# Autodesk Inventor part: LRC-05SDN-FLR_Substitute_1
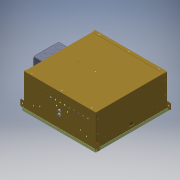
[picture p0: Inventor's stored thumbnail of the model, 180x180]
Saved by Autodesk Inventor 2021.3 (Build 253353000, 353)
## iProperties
Part Number: LRC-05SDN-FLR_Substitute_1
Material: Generic
Document SubType Name: Modeling
Designer: JChurch
Manufacturer: Standard
Standards Organization: Custom
Density: 1 g/cm^3
Appearance: Smooth - Black
Author: JChurch
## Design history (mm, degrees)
derived "LRC-05SDN-FLR.iam"
body "Solid9"
node "830399-00-00.ipt:1"
node "881088-00-00.iam:1::830140-00-00.ipt:1"
body "Solid10"
node "881088-00-00.iam:1::850014-00-00.iam:1::805044-00-00.ipt:1"
body "Solid11"
node "881088-00-00.iam:1::850014-00-00.iam:1::805174-00-00.ipt:1"
body "Solid12"
node "881088-00-00.iam:1::850014-00-00.iam:1::502055-00-00.ipt:1"
body "Solid13"
node "881088-00-00.iam:1::850014-00-00.iam:1::502055-00-00.ipt:2"
body "Solid14"
node "881088-00-00.iam:1::850014-00-00.iam:1::507032-00-00.ipt:1"
body "Solid15"
node "881088-00-00.iam:1::507000-00-00.ipt:1"
body "Solid16"
node "881088-00-00.iam:1::507000-00-00.ipt:2"
body "Solid17"
node "881088-00-00.iam:1::506002-00-00.ipt:1"
body "Solid18"
node "881088-00-00.iam:1::506002-00-00.ipt:2"
body "Solid19"
node "881088-00-00.iam:1::506002-00-00.ipt:3"
body "Solid20"
node "881088-00-00.iam:1::506002-00-00.ipt:4"
body "Solid21"
node "881088-00-00.iam:1::506002-00-00.ipt:5"
body "Solid22"
node "881088-00-00.iam:1::506002-00-00.ipt:6"
body "Solid23"
node "881088-00-00.iam:1::506002-00-00.ipt:7"
body "Solid24"
node "881088-00-00.iam:1::506002-00-00.ipt:8"
body "Solid25"
node "881088-00-00.iam:1::506002-00-00.ipt:9"
body "Solid26"
node "881088-00-00.iam:1::506002-00-00.ipt:10"
body "Solid27"
node "881088-00-00.iam:1::506002-00-00.ipt:11"
body "Solid28"
node "881088-00-00.iam:1::506002-00-00.ipt:12"
body "Solid29"
node "881088-00-00.iam:1::506002-00-00.ipt:13"
body "Solid30"
node "881088-00-00.iam:1::506002-00-00.ipt:14"
body "Solid31"
node "881088-00-00.iam:1::830392-01-00.iam:1::830392-00-00.ipt:1"
body "Solid32"
node "881088-00-00.iam:1::830392-01-00.iam:1::500027-00-00.ipt:1"
body "Solid33"
node "881088-00-00.iam:1::830392-01-00.iam:1::501030-00-00.ipt:1"
body "Solid34"
node "881088-00-00.iam:1::830392-01-00.iam:1::500027-00-00.ipt:2"
body "Solid35"
node "881088-00-00.iam:1::830392-01-00.iam:1::501030-00-00.ipt:2"
body "Solid36"
node "881088-00-00.iam:1::830392-01-00.iam:1::501030-00-00.ipt:3"
body "Solid37"
node "881088-00-00.iam:1::830392-01-00.iam:1::501030-00-00.ipt:4"
body "Solid38"
node "881088-00-00.iam:1::830392-01-00.iam:2::830392-00-00.ipt:1"
body "Solid39"
node "881088-00-00.iam:1::830392-01-00.iam:2::500027-00-00.ipt:1"
body "Solid40"
node "881088-00-00.iam:1::830392-01-00.iam:2::501030-00-00.ipt:1"
body "Solid41"
node "881088-00-00.iam:1::830392-01-00.iam:2::500027-00-00.ipt:2"
body "Solid42"
node "881088-00-00.iam:1::830392-01-00.iam:2::501030-00-00.ipt:2"
body "Solid43"
node "881088-00-00.iam:1::830392-01-00.iam:2::501030-00-00.ipt:3"
body "Solid44"
node "881088-00-00.iam:1::830392-01-00.iam:2::501030-00-00.ipt:4"
body "Solid45"
node "750032-00-XX.iam:1::710018-00-XX.ipt:1"
body "Solid46"
node "750032-00-XX.iam:1::507035-01-38.ipt:1"
body "Solid47"
node "750032-00-XX.iam:1::805206-00-00.ipt:1"
body "Solid48"
node "750032-00-XX.iam:1::502040-00-00.ipt:1"
body "Solid49"
node "750032-00-XX.iam:1::507014-00-00.ipt:1"
body "Solid50"
node "750032-00-XX.iam:1::805206-00-00.ipt:2"
body "Solid51"
node "750032-00-XX.iam:1::507035-01-38.ipt:2"
body "Solid52"
node "750032-00-XX.iam:1::502040-00-00.ipt:2"
body "Solid53"
node "750032-00-XX.iam:1::507014-00-00.ipt:2"
body "Solid54"
node "725377-00-00.ipt:1"
body "Solid55"
other parameters: "d15" = 61.595, "d16" = 9.525, "d17" = 9.525, "d35" = 5.08
